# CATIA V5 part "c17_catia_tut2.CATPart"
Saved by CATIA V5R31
Part number: Part1
Bounding box of the stored display mesh (mm): x -65 to 65, y -120 to 120, z -37.621 to 37.5
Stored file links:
  D:\PROJECTS\Project 2021\US EDITION\CATIA V5 6R 2021\Resources\Tutorial Files\c17_catia_v5_6r2021_tut\c17_catia_tut2.CATPart
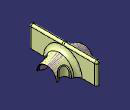
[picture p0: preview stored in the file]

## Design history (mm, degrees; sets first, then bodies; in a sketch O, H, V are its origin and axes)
Body1 (main body)
  Sketch1 on zx-plane, origin (0, 0, 0), H (-1, 0, 0), V (0, 0, 1)
    line L1 (7.5, 37.5) -> (7.5, -37.5)
    line L2 (-7.5, -37.5) -> (-7.5, 37.5)
    line L3 (-7.5, 37.5) -> (7.5, 37.5)
    point P2 (7.5, -37.5)
    distance L1 L2 = 15
    length L1 = 75
    distance H P2 = 37.5
    vertical: L1 V, L2 V
    horizontal: L3 H
    equidistance: L1 L2 O
  Extrude1: Element1 Sketch1, Lim1 120, Lim2 120
  Sketch2 on face of Extrude1 from Sketch1.L2, origin (7.5, 0, 0), H (0, -1, 0), V (0, 0, 1)
    arc A1 centre (0, -37.6505) radius 55 from (55, -37.6505) to (-55, -37.6505) ccw
    point P1 (0, -37.6505)
    axis line L1 (-118.7489, -37.6505) -> (99.6231, -37.6505)
    point P4 (-55, -37.6505)
    point P5 (55, -37.6505)
    radius A1 = 55
    coincidence: P1 V, L1 P4, L1 P5
    horizontal: L1 H
  Plane1: type Offset, RefPlane yz-plane, Offset 65
  Sketch3 on Plane1, origin (65, 0, 0), H (0, 1, 0), V (0, 0, 1)
    arc A1 centre (0, -37.9724) radius 35 from (34.9968, -37.5) to (-34.9968, -37.5) ccw
    point P1 (0, -37.9724)
    axis line L1 (106.4819, -37.5) -> (-95.6002, -37.5)
    reference projected line E1 (-120, -37.5) -> (120, -37.5) from edge of Extrude1
    point P4 (-34.9968, -37.5)
    point P5 (34.9968, -37.5)
    radius A1 = 35
    coincidence: P1 V, L1 E1, L1 P4, L1 P5
    horizontal: L1 H
  Loft1: Sections (Sketch3; Sketch2)
  Symmetry1: ToTransfor Loft1, Reference yz-plane
  Line1: type PtPt, FirstPoint vertex [face of Extrude1 from Sketch1.L2], SecondPoint vertex [face of Extrude1 from Sketch1.L1]
  Fill1: Boundary (edge of Extrude1; edge of Extrude1; edge of Extrude1; Line1)
  Line2: type PtPt, FirstPoint vertex [face of Extrude1 from Sketch1.L1], SecondPoint vertex [face of Extrude1 from Sketch1.L2]
  Fill2: Boundary (edge of Extrude1; edge of Extrude1; edge of Extrude1; Line2)
  Trim1: Trimmed (Loft1; Extrude1)
  Trim2: Trimmed (Symmetry1; Trim1)
  Join1: Elements (Fill1; Trim2; Fill2)
  Sketch4 on xy-plane, origin (0, 0, 0), H (1, 0, 0), V (0, 1, 0)
    circle A1 centre (43, 42) radius 15
    point P1 (43, 42)
    circle A2 centre (43, -42) radius 15
    distance P1 H = 42
    radius A1 = 15
    symmetry: A1 A2 H
  Extrude2: Element1 Sketch4, Lim1 40, Lim2 0, FirstUpto vertex [face of Loft1]
  Trim3: Trimmed (Extrude2; Join1)
  Fillet1: radius 18, on edge [face of Extrude1 from Sketch1.L2 | face of Loft1]; edge [face of Symmetry1 | face of Extrude1 from Sketch1.L1]
  Fillet2: radius 4, on edge [face of Loft1 | face of Extrude2 from Sketch4.A1]
  Fillet3: radius 7.5, on edge [face of Fill1 | face of Extrude1 from Sketch1.L3]; edge [face of Extrude1 from Sketch1.L3 | face of Fill2]; edge [face of Extrude1 from Sketch1.L2 | face of Extrude1 from Sketch1.L3]; edge [face of Extrude1 from Sketch1.L3 | face of Extrude1 from Sketch1.L1]; edge [face of Extrude1 from Sketch1.L2 | face of Fill2]; edge [face of Fill1 | face of Extrude1 from Sketch1.L2]; edge [face of Fill1 | face of Extrude1 from Sketch1.L1]; edge [face of Extrude1 from Sketch1.L1 | face of Fill2]
  Fillet4: radius 4, on edge [face of Extrude2 from Sketch4.A2 | face of Loft1]
  Set1
    ThickSurface1: BotOffset 0, Surface Fillet4, TopOffset 1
